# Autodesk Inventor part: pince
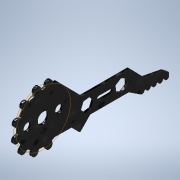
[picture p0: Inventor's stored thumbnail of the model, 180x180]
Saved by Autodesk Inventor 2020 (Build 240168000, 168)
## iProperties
Created: 2021-10
Part Number: pince
Material: Générique
Document SubType Name: Modeling
Designer: bruno
Density: 1 g/cm^3
Appearance: Noir
Author: bruno
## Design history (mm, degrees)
sketch "Esquisse1"
  geometry: L1 (-0.244, -38.167)-(-0.244, -17.144); L2 (-9.818, -12.478)-(-13.216, -15.844); L3 (-6.724, -44.413)-(-8.393, -53.057); L4 (-8.393, -53.057)-(-10.196, -55.455); L5 (-10.196, -55.455)-(-11.607, -55.455); L6 (0, 7)-(0, -8.75); L7 (-12.196, -55.455)-(-12.196, -55.476); L8 (-11.599, -44.655)-(-11.599, -45.356); L9 (11.244, 3.975)-(10.788, 3.82); L10 (11.864, 1.062)-(11.343, 0.947); L11 (10.951, 0.571)-(10.951, 0.458); L12 (9.199, 5.97)-(9.255, 5.873); L13 (9.743, 6.851)-(9.35, 6.491); L14 (7.75, 9.065)-(7.433, 8.702); L15 (4.981, 9.77)-(5.079, 9.713); L16 (5.012, 10.805)-(4.852, 10.297); L17 (2.179, 11.726)-(2.086, 11.252); L18 (-0.571, 10.951)-(-0.458, 10.951); L19 (-1.062, 11.864)-(-0.947, 11.343); L20 (-3.975, 11.244)-(-3.82, 10.788); L21 (-5.97, 9.199)-(-5.873, 9.255); L22 (-6.851, 9.743)-(-6.491, 9.35); L23 (-9.065, 7.75)-(-8.702, 7.433); L24 (-9.77, 4.981)-(-9.713, 5.079); L25 (-10.805, 5.012)-(-10.297, 4.852); L26 (-11.726, 2.179)-(-11.252, 2.086); L27 (-10.951, -0.571)-(-10.951, -0.458); L28 (-11.864, -1.062)-(-11.343, -0.947); L29 (-11.244, -3.975)-(-11.288, -3.99); L30 (10.167, -4.111)-(10.119, -4.213); L31 (11.871, -1.149)-(11.391, -1.097); L32 (11.201, -4.051)-(10.681, -3.936); L33 (24.231, -59.591)-(24.231, 5.458); L34 (24.231, 5.458)-(-15.993, 5.458); L35 (-15.993, 5.458)-(-15.993, -59.591); L36 (-15.993, -59.591)-(24.231, -59.591); L37 (-13.213, -16.557)-(-8.957, -20.692); L38 (-8.957, -20.692)-(-8.957, -37.719); L39 (-11.607, -52.755)-(-11.607, -53.455); L40 (-11.607, -47.355)-(-11.607, -48.055); L41 (-11.607, -50.055)-(-11.607, -50.755); L42 (-11.599, -44.208)-(-11.607, -44.193); L43 (-4.7, -24.661)-(-4.7, -29.925); L44 (-5.7, -24.661)-(-5.7, -29.925); L45 (-3.7, -29.925)-(-3.7, -24.661); L46 (-0.244, -38.167)-(-0.244, -38.182); L47 (-9.818, -12.478)-(-9.733, -5.173); L48 (-10.788, -3.82)-(-11.288, -3.99); L49 (10.946, -6.1)-(-0.244, -17.144); L50 (10.946, -0.574)-(10.946, -0.626); L51 (10.946, -4.623)-(10.946, -6.1); L52 (-11.607, -54.455)-(-11.207, -54.455); L53 (-0.244, -38.182)-(-6.742, -44.504); L54 (-12.464, -43.067)-(-8.957, -37.719); C1 r 2.5 at (0, 0); C2 r 1.75 at (0, 7); A1 r 1.75 centre (0, -7) between (0, -8.75) and (1.658, -7.559); A2 r 1 centre (-11.657, -43.657) between (-12.464, -43.067) and (-11.599, -44.655); A3 r 1 centre (-11.573, -46.355) between (-11.599, -45.356) and (-11.607, -47.355); A4 r 1 centre (-11.607, -49.055) between (-11.607, -48.055) and (-11.607, -50.055); A5 r 1 centre (-11.607, -51.755) between (-11.607, -50.755) and (-11.607, -52.755); A6 r 1 centre (-11.607, -54.455) between (-11.607, -53.455) and (-11.607, -55.455); A7 r 1.5 centre (11.729, 2.556) between (11.864, 1.062) and (11.244, 3.975); A8 r 0.5 centre (10.627, 4.293) between (10.163, 4.106) and (10.788, 3.82); A9 r 0.5 centre (11.451, 0.458) between (11.343, 0.947) and (10.951, 0.458); A10 r 0.5 centre (9.688, 6.123) between (9.35, 6.491) and (9.255, 5.873); A11 r 1.5 centre (8.879, 8.078) between (9.743, 6.851) and (7.75, 9.065); A12 r 0.5 centre (7.056, 9.031) between (6.749, 8.637) and (7.433, 8.702); A13 r 0.5 centre (5.329, 10.146) between (4.852, 10.297) and (5.079, 9.713); A14 r 1.5 centre (3.651, 11.435) between (5.012, 10.805) and (2.179, 11.726); A15 r 0.5 centre (1.595, 11.349) between (1.526, 10.854) and (2.086, 11.252); A16 r 0.5 centre (-0.458, 11.451) between (-0.947, 11.343) and (-0.458, 10.951); A17 r 1.5 centre (-2.556, 11.729) between (-1.062, 11.864) and (-3.975, 11.244); A18 r 0.5 centre (-4.293, 10.627) between (-4.106, 10.163) and (-3.82, 10.788); A19 r 0.5 centre (-6.123, 9.688) between (-6.491, 9.35) and (-5.873, 9.255); A20 r 1.5 centre (-8.078, 8.879) between (-6.851, 9.743) and (-9.065, 7.75); A21 r 0.5 centre (-9.031, 7.056) between (-8.637, 6.749) and (-8.702, 7.433); A22 r 0.5 centre (-10.146, 5.329) between (-10.297, 4.852) and (-9.713, 5.079); A23 r 1.5 centre (-11.435, 3.651) between (-10.805, 5.012) and (-11.726, 2.179); A24 r 0.5 centre (-11.349, 1.595) between (-10.854, 1.526) and (-11.252, 2.086); A25 r 0.5 centre (-11.451, -0.458) between (-11.343, -0.947) and (-10.951, -0.458); A26 r 1.5 centre (-11.729, -2.556) between (-11.864, -1.062) and (-11.244, -3.975); A27 r 0.5 centre (-10.627, -4.293) between (-10.163, -4.106) and (-10.788, -3.82); A28 r 0.5 centre (11.445, -0.6) between (10.946, -0.574) and (11.391, -1.097); A29 r 0.5 centre (10.572, -4.424) between (10.681, -3.936) and (10.119, -4.213); A30 r 1.5 centre (11.71, -2.64) between (11.512, -4.127) and (11.871, -1.149); A31 r 10.961 centre (0, 0) between (-10.854, 1.526) and (-10.951, -0.458); A32 r 10.961 centre (0, 0) between (-8.637, 6.749) and (-9.713, 5.079); A33 r 10.961 centre (0, 0) between (-4.106, 10.163) and (-5.873, 9.255); A34 r 10.961 centre (0, 0) between (1.526, 10.854) and (-0.458, 10.951); A35 r 10.961 centre (0, 0) between (10.163, 4.106) and (9.255, 5.873); A36 r 10.961 centre (0, 0) between (6.749, 8.637) and (5.079, 9.713); A37 r 0.5 centre (-12.864, -16.199) between (-13.216, -15.844) and (-13.213, -16.557); A38 r 1 centre (-4.7, -24.661) between (-3.7, -24.661) and (-5.7, -24.661); A39 r 1 centre (-4.7, -29.925) between (-5.7, -29.925) and (-3.7, -29.925); A40 r 7.739 centre (0, 0) between (5.487, 5.458) and (1.658, -7.559); A41 r 0.5 centre (-10.222, -4.155) between (-9.722, -4.161) and (-10.383, -3.682); A42 r 0.5 centre (11.446, -4.623) between (11.512, -4.127) and (10.946, -4.623); A43 r 10.964 centre (0, 0) between (10.946, -0.626) and (10.951, 0.523); A44 r 10.964 centre (0, 0) between (10.135, -4.181) and (10.146, -4.155); A45 r 10.964 centre (0, 0) between (10.185, 4.058) and (9.223, 5.928); A46 r 10.964 centre (0, 0) between (6.791, 8.607) and (5.023, 9.745); A47 r 10.964 centre (0, 0) between (1.578, 10.85) and (-0.523, 10.951); A48 r 10.964 centre (0, 0) between (-4.058, 10.185) and (-5.928, 9.223); A49 r 10.964 centre (0, 0) between (-8.607, 6.791) and (-9.745, 5.023); A50 r 10.964 centre (0, 0) between (-10.85, 1.578) and (-10.951, -0.523); A51 r 10.964 centre (0, 0) between (-10.185, -4.058) and (-9.787, -4.942); A52 r 0.5 centre (-10.233, -5.167) between (-9.733, -5.173) and (-9.787, -4.942); 28 further points; 1 other entity
  constraints: 116 point on circle, 102 end point, 54 centre point, 27 point on line, 17 tangent, 7 vertical, 4 coincident, 4 perpendicular, 2 horizontal, 2 parallel, 1 midpoint, 123 other
  dimensions: "d0" = 5 diameter of C1; "d1" = 3.5 diameter of C2; "d2" = 3.5 diameter of A1; "d3" = 7 distance of point (0, 0) L6.start; "d4" = 7 distance of point (0, 0) A1.centre; "d17" = 3 distance of L3.end L4.end; "d18" = 2 distance of L7.end L4.end; "d20" = 2 diameter of A3; "d21" = 2 diameter of A2; "d22" = 2 diameter of A4; "d24" = 2 diameter of A5; "d25" = 2.7 distance of A2.centre A3.centre; "d26" = 2.7 distance of A3.centre A4.centre; "d27" = 2.7 distance of A5.centre A4.centre; "d28" = 2 diameter of A6; "d29" = 2.7 distance of L52.start A5.centre; "d30" = 3 diameter of A7; "d31" = 0.5 radius of A8 (derived); "d32" = 0.5 radius of A9 (derived); "d35" = 180 deg dimension on A31.centre A9.centre A25.centre; "d39" = 25 deg dimension on C1.centre L30.start L11.start; "d132" = 0.5 radius of A37 (derived); "d136" = 2 diameter of A39; "d154" = 0.5 radius of A41 (derived); "d156" = 0.5 radius of A42 (derived); "d167" = 0.5 radius of A52 (derived); "d178" = 0.4 distance of L52.start L52.end
extrude "Extrusion2" new body sketch "Esquisse1" distance "d48" = 1; taper "d49" = 0 deg
sketch "Esquisse2"
  geometry: L1 (21.242, -7.012)-(18.385, -7.425); L2 (18.385, -7.425)-(16.598, -5.157); L3 (16.598, -5.157)-(17.669, -2.476); L4 (17.669, -2.476)-(20.526, -2.063); L5 (20.526, -2.063)-(22.312, -4.331); L6 (22.312, -4.331)-(21.242, -7.012); L7 (34.555, -7.629)-(32.006, -6.273); L8 (32.006, -6.273)-(31.907, -3.388); L9 (31.907, -3.388)-(34.356, -1.859); L10 (34.356, -1.859)-(36.904, -3.215); L11 (36.904, -3.215)-(37.003, -6.1); L12 (37.003, -6.1)-(34.555, -7.629); L13 (55.455, -11.607)-(55.455, -10.196) reference; L14 (20.692, -8.957)-(37.719, -8.957) reference; 9 further points; 1 other entity
  constraints: 24 end point, 27 other
  dimensions: "d50" = 5 distance between parallel lines of L5 L2; "d51" = 5 distance between parallel lines of L8 L11; "d56" = 15 distance of point (19.455, -4.744) point (34.455, -4.744); "d57" = 21 distance from line of L13 point (34.455, -4.744); "d171" = 4.5 dimension on point (19.455, -4.744); "d172" = 4.5 dimension on point (34.455, -4.744)
extrude "Extrusion3" cut sketch "Esquisse2" distance "d54" = 10; taper "d55" = 0 deg
sketch "Esquisse3"
  geometry: C1 r 12 at (0, 0); 1 further point
  constraints: 1 centre point, 1 coincident
  dimensions: "d62" = 24 diameter of C1
feature "SrfExtrusion1" sketch "Esquisse3" dims "d63" = 1, "d64" = 0
node "Solide2"
body "Srf1"
node "Image1"
other parameters: "d5" = 22.5
